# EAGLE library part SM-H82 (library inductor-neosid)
FILTER SMD helical filter
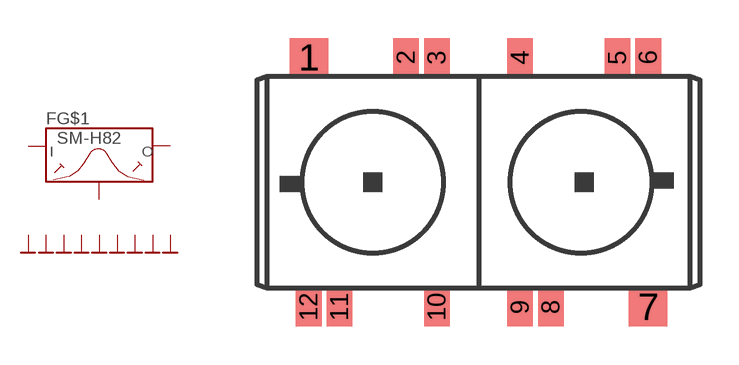
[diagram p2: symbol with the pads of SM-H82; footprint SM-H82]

Designator prefix F; gates G$1=HELIX-FI GND3=GND GND4=GND GND5=GND GND6=GND GND8=GND GND9=GND GND10=GND GND11=GND GND12=GND

## SM-H82 (OC_FARNELL: unknown; OC_NEWARK: unknown)  [SM-H82]
1  G$1:IN  pas
2  G$1:GND  pwr
3  GND3:GND  pwr
4  GND4:GND  pwr
5  GND5:GND  pwr
6  GND6:GND  pwr
7  G$1:OUT  pas
8  GND8:GND  pwr
9  GND9:GND  pwr
10  GND10:GND  pwr
11  GND11:GND  pwr
12  GND12:GND  pwr

## Footprint SM-H82 (pad centres in mm)
SMD HELICAL FILTER 8.45 x 17.5 x 5.4 mm
smd 1.5 x 1.5: 1 -6.625,4.875; 7 6.625,-4.875
smd 1 x 1.5: 2 -2.825,4.875; 3 -1.625,4.875; 4 1.625,4.875; 5 5.425,4.875; 6 6.625,4.875; 8 2.825,-4.875; 9 1.625,-4.875; 10 -1.625,-4.875; 11 -5.425,-4.875; 12 -6.625,-4.875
